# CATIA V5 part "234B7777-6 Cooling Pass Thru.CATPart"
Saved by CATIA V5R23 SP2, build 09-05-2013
Part number: 234B7777-6 Cooling Pass Thru
Publications: "Layup Surface above Pass Through"
Material "Brushed metal 2": density 7860 kg/m3, Young's modulus 2e+11 Pa, Poisson ratio 0.266
Bounding box of the stored display mesh (mm): x 31580.906 to 31914.965, y -11337.313 to -11224.158, z 5299.431 to 5325.91
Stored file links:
  C:\Users\rem1927\Desktop\Current Explicit Composite Demo\234B7777-6 Cooling Pass Thru.CATPart
  C:\Users\rem1927\Desktop\Current Explicit Composite Demo\234B5678-1 Composite Product.CATProduct
  C:\Users\rem1927\Desktop\Current Explicit Composite Demo\234B5678-3 - Above Core Laminate.CATPart
  C:\Program Files\Dassault Systemes\B23SP2PRALL\win_b64\startup\materials\Catalog.CATMaterial
  C:\Program Files\Dassault Systemes\B23SP2PRALL\win_b64\startup\materials\brushed_metal2.jpg
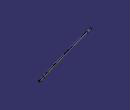
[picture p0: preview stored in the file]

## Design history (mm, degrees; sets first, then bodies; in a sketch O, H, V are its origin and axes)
Set1
  Extract1: ExtractElem edge of DatumCurve1
  CurvePar1: Offset Extract1, Support DatumSurface1, Offset2 0, Offset1 24.13
  CurvePar2: Offset CurvePar1, Support DatumSurface1, Offset2 0, Offset1 3.175
  CurvePar3: Offset CurvePar1, Support DatumSurface1, Offset2 0, Offset1 3.175
  Sweep1: type Segment, GuideCrv CurvePar3, GuideSurf DatumSurface1, Length1 3.175, Length2 0, Angle 90
  Sweep2: type Segment, GuideCrv CurvePar1, GuideSurf DatumSurface1, Length1 6.35, Length2 0, Angle 90
  Sweep3: type Segment, GuideCrv CurvePar2, GuideSurf DatumSurface1, Length1 3.175, Length2 0, Angle 90
  Boundary1: Boundary edge of Sweep3
  Boundary2: Boundary edge of Sweep2
  Boundary3: Boundary edge of Sweep1
  Split1: ToCut DatumSurface1, Cutting CurvePar1
  Fillet1: type BiTangent, Element1 Split1, Element2 Sweep1, Radius 1.27
  Fillet2: type BiTangent, Element1 {split ToCut DatumSurface1, Cutting CurvePar1}, Element2 Sweep3, Radius 1.27
  Sweep4: type Circle, Guide (Boundary3; Boundary2; Boundary1)
  CurvePar4: Offset CurvePar1, Support Sweep2, Offset2 0, Offset1 3.175
  Join1 "Layup Surface above Pass Through": Elements (Fillet1; Sweep4; Fillet2)
  Sweep5: type Circle, Guide CurvePar4, Radius 3.175
  Plane1: type 1Curve, Element1 edge of Sweep5
  Point1: type OnCurve, Support CurvePar4, Ratio 1
  Point2: type OnCurve, Support CurvePar4, Ratio 0
  Line1: type PtDir, RefPoint Point1, Direction Plane1, Start 0, End 25.4
  Plane2: type 1Curve, Element1 edge of Sweep4
  Line2: type PtDir, RefPoint Point2, Direction Plane2, Start 0, End 25.4
  Join2: Elements (Line2; CurvePar4; Line1)
  Sweep6: type Circle, Guide Join2, Radius 3.175
Set2
  DatumCurve1: linked copy from another document
  DatumSurface1 "Layup for systems": linked copy from another document
Body1 "Cooling Pass Thru" (main body), material "Brushed metal 2"
  ThickSurface1: BotOffset 0, Surface Sweep6, TopOffset 0.635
